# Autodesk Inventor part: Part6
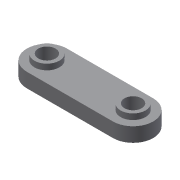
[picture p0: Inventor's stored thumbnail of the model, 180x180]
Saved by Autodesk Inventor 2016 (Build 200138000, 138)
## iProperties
Shininess: 77.0
Length Units: 11269
Angle Units: 11279
Time Units: 11290
Mass Units: 11283
Length Display Precision: 3
Angle Display Precision: 2
Created: 2002-01
Part Number: Part6
Document SubType Name: Modeling
Designer: ***
Density: 1 g/cm^3
Mass: 21.6911 g
Surface Area: 77.1136 cm^2
Volume: 21.6911 cm^3
Material: Generic
Appearance: Default
Density: 0.0
Volumn: 0.0
Area: 0.0
PropertySet Name: Model Information
Control State: 0
Master: False
Checked Out: False
Author: ***
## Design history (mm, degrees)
sketch "Sketch1"
  geometry: L1 (-33.118, 12.346)-(26.882, 12.361); L2 (-33.111, -15.654)-(26.889, -15.639); C1 r 6 at (-33.114, -1.654); C2 r 6 at (26.886, -1.639); A1 r 14 centre (-33.114, -1.654) between (-33.118, 12.346) and (-33.111, -15.654); A2 r 14 centre (26.886, -1.639) between (26.889, -15.639) and (26.882, 12.361)
  constraints: 4 centre point, 4 end point, 4 point on circle, 4 tangent, 2 coincident, 2 equal radius
  dimensions: "d0" = 60 distance of L1.start L1.end; "d1" = 14 radius of A1; "d2" = 12 diameter of C1
extrude "Extrusion1" new body sketch "Sketch1" distance "d3" = 10; taper "d4" = 0 deg
sketch "Sketch2"
  geometry: C1 r 6 at (26.886, -1.639) reference; C2 r 6 at (-33.114, -1.654) reference; C3 r 8.694 at (-33.114, -1.654); C4 r 8.694 at (26.886, -1.639)
  constraints: 2 centre point, 2 coincident, 1 equal radius
extrude "Extrusion2" join sketch "Sketch2" distance "d5" = 4; taper "d6" = 0 deg
body "Solid1"
